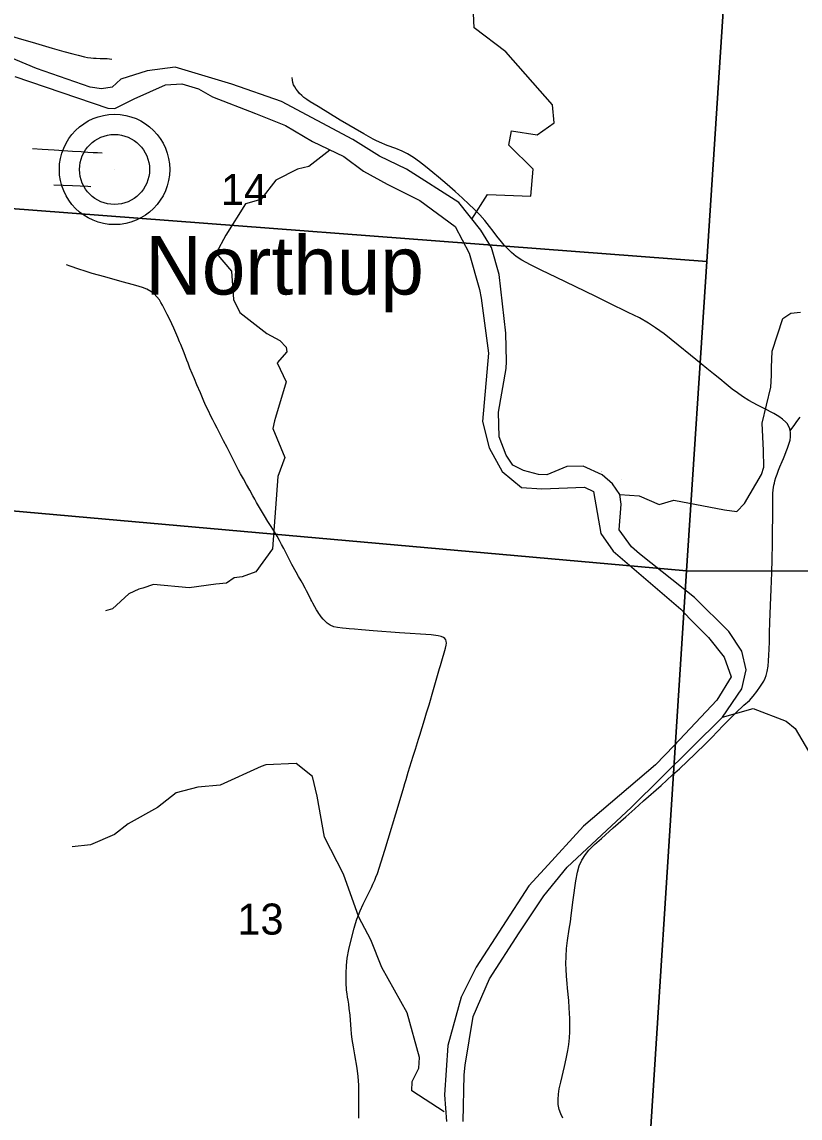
# Model space of a CAD drawing. Extents: x 0 to 34, y 0 to 22.
# Drawn here: x 3.059 to 4.109, y 16.271 to 17.749 of the extents above; entities that cross this region are included whole.
import ezdxf

# ---------------------------------------------------------------- set-up
doc = ezdxf.new("R2010")
doc.units = 0
for name, color, linetype in [('GM_X_County_Road', 7, 'Continuous'), ('GM_X_Major_River', 7, 'Continuous'), ('GM_X_Minor_River', 7, 'Continuous'), ('GM_X_Section', 7, 'Continuous'), ('GM_X_Section_Text', 7, 'Continuous'), ('GM_X_Township_Road', 7, 'Continuous'), ('GM_X_Unincorporated', 7, 'Continuous'), ('GM_X_Unincorporated_Location', 7, 'Continuous'), ('GM_X_Unincorporated_Text', 7, 'Continuous')]:
    doc.layers.add(name, color=color, linetype=linetype)

msp = doc.modelspace()

# ---------------------------------------------------------------- linework, layer by layer
at = {"layer": 'GM_X_County_Road'}
for points in [[(2.9595, 17.7514), (2.994, 17.7433), (3.0145, 17.738), (3.0299, 17.7343), (3.0455, 17.7298), (3.0589, 17.7258), (3.0732, 17.7216), (3.1003, 17.7139), (3.1161, 17.7094), (3.1283, 17.7061), (3.1352, 17.7041), (3.1437, 17.7021), (3.1478, 17.7012), (3.1524, 17.7005), (3.1562, 17.7002), (3.1594, 17.7001), (3.1652, 17.7), (3.1715, 17.7), (3.1745, 17.6998), (3.1775, 17.6995), (3.1809, 17.6989)], [(3.789, 16.2704), (3.7863, 16.2764), (3.784, 16.2824), (3.7826, 16.2889), (3.7824, 16.2957), (3.7829, 16.3028), (3.7839, 16.3101), (3.7862, 16.3192), (3.7912, 16.34), (3.7935, 16.3507), (3.7958, 16.3618), (3.7969, 16.3699), (3.798, 16.3789), (3.7982, 16.387), (3.7983, 16.3951), (3.7983, 16.4051), (3.7974, 16.4193), (3.7968, 16.4293), (3.7953, 16.446), (3.7948, 16.4522), (3.7939, 16.4621), (3.7935, 16.4713), (3.7931, 16.4788), (3.7932, 16.4887), (3.7939, 16.4992), (3.7953, 16.5102), (3.7976, 16.5256), (3.7992, 16.5354), (3.8003, 16.544), (3.8028, 16.565), (3.8064, 16.5904), (3.8085, 16.6021), (3.811, 16.6109), (3.8143, 16.6186), (3.8194, 16.626), (3.824, 16.6319), (3.8316, 16.6396), (3.841, 16.6478), (3.8566, 16.662), (3.8739, 16.6771), (3.886, 16.6878), (3.8977, 16.6984), (3.9215, 16.719), (3.9369, 16.7335), (3.946, 16.7418), (3.9673, 16.7618), (3.9816, 16.7757), (3.9898, 16.7841), (3.9976, 16.7922), (4.0053, 16.8003), (4.014, 16.8091), (4.0222, 16.8173), (4.0331, 16.8274), (4.0405, 16.8338), (4.0457, 16.8396), (4.0505, 16.8461), (4.0555, 16.8533), (4.0599, 16.86), (4.0617, 16.864), (4.063, 16.8675), (4.0645, 16.8728), (4.0656, 16.88), (4.0663, 16.8874), (4.0668, 16.8948), (4.0672, 16.9029), (4.0675, 16.9128), (4.0676, 16.9171), (4.0678, 16.9252), (4.0682, 16.9395), (4.0691, 16.9618), (4.07, 16.9842), (4.0703, 16.9947), (4.0706, 17.0063), (4.0711, 17.0239), (4.0717, 17.0456), (4.0718, 17.0561), (4.0717, 17.0648), (4.0721, 17.0791), (4.0719, 17.1045), (4.0722, 17.1131), (4.0726, 17.118), (4.073, 17.1211), (4.0734, 17.1241), (4.0742, 17.127), (4.0749, 17.13), (4.0762, 17.1347), (4.078, 17.1393), (4.0798, 17.1445), (4.0817, 17.1491), (4.0847, 17.1564), (4.0864, 17.1604), (4.0881, 17.1646), (4.0901, 17.1698), (4.092, 17.1744), (4.0937, 17.1797), (4.0953, 17.1851), (4.0959, 17.1895), (4.096, 17.192), (4.0959, 17.1958), (4.0954, 17.1978), (4.0949, 17.2001), (4.0936, 17.2036), (4.0912, 17.2074), (4.0896, 17.2093), (4.0853, 17.2131), (4.0803, 17.2168), (4.0733, 17.2209), (4.0605, 17.2275), (4.0512, 17.2323), (4.0398, 17.2386), (4.0314, 17.2438), (4.0243, 17.2487), (4.0173, 17.2539), (4.009, 17.2605), (4.0005, 17.2675), (3.9922, 17.2743), (3.9833, 17.2815), (3.9754, 17.288), (3.9612, 17.2996), (3.9445, 17.3131), (3.9255, 17.3282), (3.9139, 17.3366), (3.9045, 17.3427), (3.8921, 17.3498), (3.8771, 17.3574), (3.8514, 17.3699), (3.8335, 17.3786), (3.8056, 17.3921), (3.7804, 17.4043), (3.7596, 17.4141), (3.7452, 17.4213), (3.7338, 17.4277), (3.7261, 17.4328), (3.7199, 17.4379), (3.7137, 17.4439), (3.71, 17.4481), (3.7063, 17.4523), (3.7001, 17.4602), (3.6949, 17.467), (3.6898, 17.4734), (3.6837, 17.4811), (3.6772, 17.4887), (3.6694, 17.4967), (3.6621, 17.5035), (3.6535, 17.5115), (3.6437, 17.5203), (3.633, 17.5297), (3.6212, 17.5398), (3.6136, 17.5462), (3.6039, 17.554), (3.5956, 17.5605), (3.5875, 17.5663), (3.5794, 17.5711), (3.5722, 17.5747), (3.5635, 17.5782), (3.5519, 17.5826), (3.5416, 17.5869), (3.5366, 17.5893), (3.5333, 17.591), (3.5268, 17.5944), (3.5206, 17.598), (3.4885, 17.6165), (3.4588, 17.6349), (3.4481, 17.6415), (3.4436, 17.6446), (3.4398, 17.6474), (3.4368, 17.65), (3.4339, 17.6528), (3.4314, 17.6555), (3.4292, 17.6585), (3.4274, 17.6614), (3.4259, 17.6643), (3.4248, 17.6675), (3.4242, 17.6706), (3.4238, 17.6743)]]:
    msp.add_lwpolyline(points, dxfattribs=at)
at = {"layer": 'GM_X_Major_River'}
for points in [[(3.7128, 17.291), (3.7119, 17.3294), (3.703, 17.4086), (3.6926, 17.4447), (3.6785, 17.4681), (3.6485, 17.5056), (3.5779, 17.5505), (3.5419, 17.5682), (3.5055, 17.5905), (3.4095, 17.6417), (3.3427, 17.665), (3.2661, 17.6882), (3.2283, 17.6832), (3.1927, 17.672), (3.181, 17.661), (3.1666, 17.6587), (3.1514, 17.6609), (3.079, 17.6864), (2.9728, 17.7308)], [(3.0499, 17.6753), (3.1754, 17.6329), (3.1848, 17.6325), (3.2109, 17.6455), (3.2533, 17.6643), (3.2753, 17.6655), (3.2977, 17.6588), (3.3166, 17.6482), (3.3743, 17.6257), (3.4149, 17.6095), (3.4513, 17.588), (3.4938, 17.5676), (3.52, 17.5476), (3.5522, 17.5303), (3.5962, 17.5084), (3.6437, 17.4733), (3.6627, 17.4373), (3.6765, 17.3881), (3.6788, 17.3763), (3.6885, 17.3023), (3.6804, 17.2101), (3.6896, 17.1748), (3.7071, 17.1427), (3.7333, 17.1211), (3.7606, 17.1193), (3.8182, 17.1218), (3.8303, 17.1158), (3.8403, 17.0589), (3.8567, 17.0354), (3.9482, 16.9572), (3.9608, 16.9436), (3.9854, 16.919), (4.0064, 16.8925), (4.0159, 16.8656), (3.9967, 16.8344), (3.9389, 16.7731), (3.914, 16.7472), (3.8168, 16.6645), (3.7643, 16.607), (3.7432, 16.5838), (3.6719, 16.4743), (3.6516, 16.4336), (3.634, 16.3683), (3.6292, 16.3018), (3.632, 16.2662)], [(3.6547, 16.2662), (3.656, 16.3289), (3.6571, 16.3418), (3.6679, 16.4078), (3.6901, 16.4584), (3.7301, 16.5204), (3.7633, 16.5706), (3.7946, 16.609), (3.8812, 16.6894), (4.0043, 16.8113), (4.0304, 16.8497), (4.0363, 16.8752), (4.0302, 16.9006), (4.0127, 16.9267), (3.9664, 16.9728), (3.8923, 17.0318), (3.8817, 17.0412), (3.8649, 17.0639), (3.8675, 17.0988), (3.8656, 17.1117), (3.8557, 17.1261), (3.842, 17.1382), (3.8162, 17.1499), (3.7942, 17.1494), (3.7674, 17.1383), (3.756, 17.1387), (3.7359, 17.1439), (3.7215, 17.1514), (3.7124, 17.1647), (3.7032, 17.1893), (3.702, 17.2227), (3.7124, 17.2816), (3.7128, 17.291)]]:
    msp.add_lwpolyline(points, dxfattribs=at)
at = {"layer": 'GM_X_Minor_River'}
for points in [[(3.6664, 17.483), (3.6872, 17.5164), (3.7457, 17.5142), (3.749, 17.5507), (3.716, 17.5827), (3.7199, 17.6024), (3.7545, 17.5967), (3.7771, 17.6132), (3.7749, 17.6375), (3.712, 17.7086), (3.6695, 17.7413), (3.6631, 17.8798)], [(3.4745, 17.5761), (3.4465, 17.5542), (3.4313, 17.5504), (3.4021, 17.5355), (3.3817, 17.5096), (3.3612, 17.5039), (3.3343, 17.4617), (3.3214, 17.4373), (3.3422, 17.413), (3.3448, 17.3746), (3.3532, 17.3571), (3.3899, 17.329), (3.4074, 17.3192), (3.4157, 17.3104), (3.4168, 17.304), (3.4036, 17.2891), (3.4157, 17.2637), (3.4013, 17.2157), (3.4001, 17.2112), (3.3979, 17.2005), (3.4141, 17.1614), (3.4047, 17.1359), (3.3974, 17.0386), (3.375, 17.0074), (3.3565, 17.0005), (3.3458, 16.9993), (3.3352, 16.9921), (3.3208, 16.9906), (3.2852, 16.986), (3.2367, 16.9901), (3.2226, 16.9855), (3.2173, 16.984), (3.2037, 16.9775), (3.1817, 16.9577), (3.1722, 16.9547)], [(3.8656, 17.1117), (3.8918, 17.1098), (3.919, 17.098), (3.9384, 17.1041), (4.007, 17.0909), (4.0237, 17.0886), (4.0339, 17.0997), (4.0567, 17.1389), (4.0601, 17.1484), (4.0597, 17.1712), (4.0578, 17.2077), (4.0696, 17.2567), (4.0704, 17.272), (4.0704, 17.283), (4.0711, 17.305), (4.0855, 17.3492), (4.0962, 17.3564), (4.1094, 17.3576)], [(3.8408, 17.1426), (3.8408, 17.1426)], [(3.8412, 17.1424), (3.8412, 17.1424)], [(3.8675, 17.1318), (3.8674, 17.1319)], [(4.0043, 16.8113), (4.0456, 16.8229), (4.0899, 16.8058), (4.102, 16.796), (4.1441, 16.7249), (4.1532, 16.6975), (4.1638, 16.628), (4.1618, 16.5766), (4.1633, 16.5226), (4.1527, 16.4835), (4.144, 16.4302), (4.1523, 16.3835), (4.167, 16.32)], [(3.6291, 16.2789), (3.5852, 16.3072), (3.5859, 16.3198), (3.5947, 16.338), (3.5954, 16.3525), (3.5791, 16.4125), (3.545, 16.4737), (3.5299, 16.511), (3.5136, 16.5414), (3.4932, 16.5995), (3.4674, 16.6493), (3.4576, 16.7048), (3.4515, 16.7314), (3.4291, 16.7489), (3.3882, 16.7469), (3.3821, 16.745), (3.3268, 16.7195), (3.2968, 16.7168), (3.2673, 16.7095), (3.2422, 16.6894), (3.2028, 16.6676), (3.1842, 16.6532), (3.152, 16.6391), (3.1274, 16.6364)]]:
    msp.add_lwpolyline(points, dxfattribs=at)
at = {"layer": 'GM_X_Section'}
for points in [[(4.0202, 18.0387), (4.4977, 18.0162), (5.0782, 18.0036), (5.0081, 16.9831), (4.4681, 17.0085), (3.9555, 17.0086), (3.9833, 17.4262), (4.01, 17.8394)], [(4.01, 17.8394), (3.9833, 17.4262), (2.9438, 17.505), (2.9705, 17.9146)], [(2.9438, 17.505), (3.9833, 17.4262), (3.9555, 17.0086), (2.9191, 17.1007)], [(2.9191, 17.1007), (3.9555, 17.0086), (3.8924, 16.0203), (2.8549, 16.0795)], [(5.0081, 16.9831), (4.9447, 15.9846), (3.8924, 16.0203), (3.9555, 17.0086), (4.4681, 17.0085)]]:
    msp.add_lwpolyline(points, close=True, dxfattribs=at)
at = {"layer": 'GM_X_Township_Road'}
for points in [[(3.0738, 17.5782), (3.0868, 17.5774), (3.1029, 17.5765), (3.1277, 17.5749), (3.1394, 17.5742), (3.1485, 17.5736), (3.1554, 17.5731), (3.1616, 17.5729), (3.1679, 17.5726)], [(3.1027, 17.5296), (3.1277, 17.5283), (3.1482, 17.5274), (3.1522, 17.5272)], [(3.6307, 16.9043), (3.6317, 16.9084), (3.632, 16.9114), (3.6318, 16.9137), (3.631, 16.9159), (3.63, 16.9173), (3.6282, 16.9187), (3.625, 16.9201), (3.6207, 16.9209), (3.6115, 16.9222), (3.5687, 16.9251), (3.5332, 16.928), (3.5172, 16.9292), (3.508, 16.9299), (3.5007, 16.9305), (3.4968, 16.9309), (3.4916, 16.9315), (3.4852, 16.9325), (3.4803, 16.9334), (3.4752, 16.9355), (3.4713, 16.938), (3.468, 16.9412), (3.4657, 16.9434), (3.4629, 16.9467), (3.4611, 16.9492), (3.4597, 16.9513), (3.4583, 16.9534), (3.4568, 16.9561), (3.4545, 16.9604), (3.4518, 16.9653), (3.4503, 16.968), (3.4492, 16.9702), (3.4458, 16.9767), (3.4433, 16.9816), (3.4413, 16.9854), (3.4379, 16.9919), (3.4361, 16.9951), (3.4326, 17.001), (3.4291, 17.0068), (3.4235, 17.0172), (3.4207, 17.0227), (3.4176, 17.0288), (3.4149, 17.0343), (3.4126, 17.0388), (3.4096, 17.0444), (3.4068, 17.0497), (3.4035, 17.0553), (3.3999, 17.0615), (3.3955, 17.0686), (3.3913, 17.0751), (3.3865, 17.0831), (3.381, 17.0921), (3.3772, 17.0985), (3.376, 17.1007), (3.3734, 17.1052), (3.3707, 17.1098), (3.3666, 17.1174), (3.3623, 17.1251), (3.3581, 17.133), (3.3544, 17.1398), (3.3517, 17.1446), (3.3474, 17.1528), (3.3448, 17.1578), (3.3406, 17.1661), (3.3362, 17.1749), (3.3313, 17.1841), (3.3285, 17.1897), (3.3263, 17.1941), (3.3241, 17.1985), (3.3227, 17.2013), (3.3198, 17.2068), (3.317, 17.2123), (3.3144, 17.2175), (3.311, 17.2244), (3.3074, 17.2313), (3.3046, 17.2377), (3.3001, 17.2487), (3.2955, 17.2596), (3.292, 17.2675), (3.2891, 17.2747), (3.2861, 17.2819), (3.2835, 17.2888), (3.2819, 17.2929), (3.2781, 17.3028), (3.2738, 17.3138), (3.2721, 17.3178), (3.2698, 17.3235), (3.2643, 17.336), (3.2588, 17.3476), (3.2554, 17.3545), (3.2519, 17.3619), (3.2491, 17.3673), (3.247, 17.3707), (3.245, 17.3741), (3.2416, 17.3785), (3.2377, 17.3823), (3.2332, 17.3855), (3.2278, 17.3885), (3.2222, 17.3908), (3.2131, 17.3935), (3.1915, 17.3996), (3.1712, 17.4051), (3.1543, 17.4098), (3.1448, 17.4128), (3.1363, 17.4156), (3.1244, 17.4199), (3.1196, 17.4215)], [(4.0954, 17.1978), (4.1016, 17.2062), (4.1046, 17.2102), (4.109, 17.2161)], [(3.514, 16.2705), (3.5139, 16.2785), (3.5138, 16.2885), (3.5136, 16.3152), (3.513, 16.3269), (3.5117, 16.338), (3.5085, 16.3557), (3.5065, 16.3667), (3.5057, 16.3715), (3.5049, 16.3765), (3.5041, 16.3843), (3.5034, 16.3907), (3.5024, 16.4026), (3.5019, 16.4093), (3.5008, 16.4184), (3.5002, 16.4241), (3.4994, 16.4295), (3.4987, 16.4339), (3.4981, 16.4384), (3.4974, 16.4431), (3.4969, 16.4537), (3.4967, 16.4657), (3.4972, 16.4765), (3.4982, 16.4865), (3.5003, 16.4982), (3.504, 16.5129), (3.5076, 16.5269), (3.5094, 16.5331), (3.5111, 16.539), (3.5133, 16.5445), (3.5154, 16.55), (3.5196, 16.559), (3.531, 16.5818), (3.5329, 16.586), (3.5353, 16.5914), (3.5369, 16.5957), (3.5388, 16.6007), (3.5487, 16.6321), (3.568, 16.6957), (3.5746, 16.7171), (3.576, 16.7218), (3.5775, 16.7271), (3.5805, 16.7373), (3.587, 16.7586), (3.5901, 16.7681), (3.5943, 16.7817), (3.596, 16.787), (3.6023, 16.8077), (3.6052, 16.8172), (3.6085, 16.8279), (3.6144, 16.8488), (3.6228, 16.8768), (3.624, 16.881), (3.6259, 16.8875), (3.6299, 16.9012), (3.6307, 16.9043)]]:
    msp.add_lwpolyline(points, dxfattribs=at)
at = {"layer": 'GM_X_Unincorporated'}
for radius in [0.0744, 0.0472]:
    msp.add_circle((3.1844, 17.5501), radius, dxfattribs=at)
at = {"layer": 'GM_X_Unincorporated_Location'}
msp.add_line((3.1844, 17.5501), (3.1844, 17.5501), dxfattribs=at)

# ---------------------------------------------------------------- texts
at = {"layer": 'GM_X_Section_Text'}
for s, p in [('14', (3.3279, 17.5022)), ('13', (3.35, 16.5181))]:
    msp.add_text(s, height=0.04186, rotation=0, dxfattribs=at).set_placement(p)
at = {"layer": 'GM_X_Unincorporated_Text'}
msp.add_text('Northup', height=0.07898, rotation=0, dxfattribs=at).set_placement((3.2258, 17.3814))

doc.saveas('drawing.dxf')
